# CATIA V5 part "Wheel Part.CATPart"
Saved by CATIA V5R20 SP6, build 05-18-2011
Part number: Wheel Part
Bounding box of the stored display mesh (mm): x -775 to 775, y -80 to 0, z 225 to 1775
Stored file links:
  E:\#01 CATIA Lecture Materials\#06 DMU\#01 DMU KIN Page01 EX01\#01 CATPart\Wheel Part.CATPart
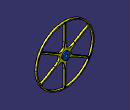
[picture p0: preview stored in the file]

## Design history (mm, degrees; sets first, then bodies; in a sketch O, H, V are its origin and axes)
Body1 (main body)
  Body2
    Sketch1 on zx-plane, origin (0, 0, 0), H (-1, 0, 0), V (0, 0, 1)
      circle A1 centre (0, 1000) radius 775
      arc A2 centre (0, 1000) radius 750 from (-35.959, 1749.1375) to (-630.7927, 1405.71) ccw
      point P1 (-35.959, 1749.1375)
      point P2 (-630.7927, 1405.71)
      line L1 (-15.0001, 1729.1605) -> (-15, 1307.7689)
      point P3 (-15.0001, 1729.1605)
      arc A3 centre (-515, 1307.8554) radius 500 from (-28.0077, 1194.5484) to (-15.0001, 1307.7689) ccw
      arc A4 centre (-9.1108, 1599.9308) radius 500 from (-259.1107, 1166.9181) to (-154.48, 1121.5296) ccw
      point P6 (-259.1107, 1166.9181)
      line L2 (-259.1107, 1166.9181) -> (-623.9715, 1377.5705)
      point P7 (-259.1107, 1166.9181)
      point P8 (-623.9715, 1377.5705)
      arc A5 centre (0, 1000) radius 750 from (-666.7516, 1343.4273) to (-666.7515, 656.5725) ccw
      point P9 (-666.7516, 1343.4273)
      point P10 (-666.7515, 656.5725)
      line L3 (-274.1107, 859.0626) -> (-638.9714, 648.4101)
      point P11 (-274.1107, 859.0626)
      point P12 (-638.9714, 648.4101)
      arc A6 centre (-524.1107, 1292.0753) radius 500 from (-274.1107, 859.0626) to (-182.4877, 926.9811) ccw
      point P13 (-274.1107, 859.0626)
      point P14 (-118.2881, 1000)
      arc A7 centre (-524.1106, 707.9246) radius 500 from (-182.4877, 1073.0188) to (-274.1622, 1140.9671) ccw
      point P15 (-118.2881, 1000)
      line L4 (-638.9715, 1351.5898) -> (-274.1622, 1140.9671)
      point P17 (-638.9715, 1351.5898)
      arc A8 centre (515, 1307.8556) radius 500 from (15, 1307.8555) to (28.0077, 1194.5484) ccw
      point P19 (15, 1307.8555)
      line L5 (15, 1307.8555) -> (14.9999, 1729.1605)
      point P20 (15, 1307.8555)
      point P21 (14.9999, 1729.1605)
      line L6 (623.9714, 1377.5707) -> (259.1106, 1166.9182)
      point P22 (623.9714, 1377.5707)
      point P23 (259.1106, 1166.9182)
      arc A9 centre (9.1106, 1599.9308) radius 500 from (154.48, 1121.5296) to (259.1106, 1166.9182) ccw
      point P24 (259.1106, 1166.9182)
      arc A10 centre (0, 1000) radius 750 from (630.7926, 1405.7102) to (35.9588, 1749.1375) ccw
      point P25 (630.7926, 1405.7102)
      point P26 (35.9588, 1749.1375)
      line L7 (274.1107, 1140.9374) -> (638.9714, 1351.5899)
      point P27 (274.1107, 1140.9374)
      point P28 (638.9714, 1351.5899)
      arc A11 centre (0, 1000) radius 750 from (666.7516, 656.5727) to (666.7515, 1343.4275) ccw
      point P29 (666.7516, 656.5727)
      point P30 (666.7515, 1343.4275)
      line L8 (638.9715, 648.4102) -> (274.1107, 859.0627)
      point P31 (638.9715, 648.4102)
      point P32 (274.1107, 859.0627)
      arc A12 centre (524.1106, 1292.0754) radius 500 from (182.4877, 926.9812) to (274.1107, 859.0627) ccw
      point P33 (274.1107, 859.0627)
      arc A13 centre (524.1107, 707.9247) radius 500 from (274.1107, 1140.9374) to (182.4877, 1073.0189) ccw
      point P34 (274.1107, 1140.9374)
      arc A14 centre (9.1108, 400.0692) radius 500 from (259.1715, 833.0468) to (154.48, 878.4704) ccw
      line L9 (259.1715, 833.0468) -> (623.9715, 622.4295)
      point P37 (623.9715, 622.4295)
      arc A15 centre (515, 692.1446) radius 500 from (28.0077, 805.4516) to (15, 692.1445) ccw
      point P38 (15, 692.1445)
      line L10 (15.0001, 270.8395) -> (15, 692.1445)
      point P39 (15.0001, 270.8395)
      point P40 (15, 692.1445)
      arc A16 centre (0, 1000) radius 750 from (35.959, 250.8625) to (630.7927, 594.29) ccw
      point P41 (35.959, 250.8625)
      point P42 (630.7927, 594.29)
      arc A17 centre (0, 1000) radius 750 from (-630.7926, 594.2898) to (-35.9588, 250.8625) ccw
      point P43 (-630.7926, 594.2898)
      point P44 (-35.9588, 250.8625)
      line L11 (-15, 692.0579) -> (-14.9999, 270.8395)
      point P46 (-14.9999, 270.8395)
      arc A18 centre (-515, 692.1444) radius 500 from (-15, 692.0579) to (-28.0077, 805.4516) ccw
      arc A19 centre (-9.1106, 400.0692) radius 500 from (-154.48, 878.4704) to (-259.1106, 833.0818) ccw
      point P48 (-259.1106, 833.0818)
      line L12 (-623.9714, 622.4293) -> (-259.1106, 833.0818)
      point P49 (-623.9714, 622.4293)
      point P50 (-259.1106, 833.0818)
      arc A20 centre (-35.0001, 1729.1605) radius 20 from (-15.0001, 1729.1605) to (-35.959, 1749.1375) ccw
      point P51 (-15.0001, 1729.1605)
      point P52 (-35.959, 1749.1375)
      circle A21 centre (-0.0001, 1750) radius 15
      arc A22 centre (34.9999, 1729.1605) radius 20 from (35.9588, 1749.1375) to (14.9999, 1729.1605) ccw
      point P53 (35.9588, 1749.1375)
      point P54 (14.9999, 1729.1605)
      circle A23 centre (-649.5191, 1374.9999) radius 15
      arc A24 centre (-613.9716, 1394.891) radius 20 from (-630.7927, 1405.71) to (-623.9715, 1377.5705) ccw
      point P55 (-630.7927, 1405.71)
      point P56 (-623.9715, 1377.5705)
      arc A25 centre (-648.9715, 1334.2693) radius 20 from (-638.9715, 1351.5898) to (-666.7516, 1343.4273) ccw
      point P57 (-638.9715, 1351.5898)
      point P58 (-666.7516, 1343.4273)
      circle A26 centre (-649.519, 624.9999) radius 15
      arc A27 centre (-613.9714, 605.1088) radius 20 from (-623.9714, 622.4293) to (-630.7926, 594.2898) ccw
      point P59 (-623.9714, 622.4293)
      point P60 (-630.7926, 594.2898)
      arc A28 centre (-648.9714, 665.7306) radius 20 from (-666.7515, 656.5725) to (-638.9714, 648.4101) ccw
      point P61 (-666.7515, 656.5725)
      point P62 (-638.9714, 648.4101)
      arc A29 centre (-34.9999, 270.8395) radius 20 from (-35.9588, 250.8625) to (-14.9999, 270.8395) ccw
      point P63 (-35.9588, 250.8625)
      point P64 (-14.9999, 270.8395)
      circle A30 centre (0.0001, 250) radius 15
      arc A31 centre (35.0001, 270.8395) radius 20 from (15.0001, 270.8395) to (35.959, 250.8625) ccw
      point P65 (15.0001, 270.8395)
      point P66 (35.959, 250.8625)
      arc A32 centre (648.9715, 665.7307) radius 20 from (638.9715, 648.4102) to (666.7516, 656.5727) ccw
      point P67 (638.9715, 648.4102)
      point P68 (666.7516, 656.5727)
      arc A33 centre (613.9716, 605.109) radius 20 from (630.7927, 594.29) to (623.9715, 622.4295) ccw
      point P69 (630.7927, 594.29)
      point P70 (623.9715, 622.4295)
      circle A34 centre (649.5191, 625.0001) radius 15
      circle A35 centre (649.519, 1375.0001) radius 15
      arc A36 centre (613.9714, 1394.8912) radius 20 from (623.9714, 1377.5707) to (630.7926, 1405.7102) ccw
      point P71 (623.9714, 1377.5707)
      point P72 (630.7926, 1405.7102)
      arc A37 centre (648.9714, 1334.2694) radius 20 from (666.7515, 1343.4275) to (638.9714, 1351.5899) ccw
      point P73 (666.7515, 1343.4275)
      point P74 (638.9714, 1351.5899)
      circle A38 centre (0, 1000) radius 100
      arc A39 centre (-125.4062, 1217.2098) radius 100 from (-28.0077, 1194.5484) to (-154.48, 1121.5296) cw
      arc A40 centre (125.4061, 1217.2098) radius 100 from (28.0077, 1194.5484) to (154.48, 1121.5296) ccw
      arc A41 centre (250.8123, 1000) radius 100 from (182.4877, 926.9812) to (182.4877, 1073.0189) cw
      arc A42 centre (125.4062, 782.7902) radius 100 from (154.48, 878.4704) to (28.0077, 805.4516) ccw
      arc A43 centre (-125.4061, 782.7902) radius 100 from (-28.0077, 805.4516) to (-154.48, 878.4704) ccw
      arc A44 centre (-250.8123, 1000) radius 100 from (-182.4877, 926.9811) to (-182.4877, 1073.0188) ccw
      radius A39 = 100
      radius A40 = 100 {= Sketch1.radius(A39)}
      radius A41 = 100 {= Sketch1.radius(A39)}
      radius A42 = 100 {= Sketch1.radius(A39)}
      radius A43 = 100 {= Sketch1.radius(A39)}
      radius A44 = 100
      tangency: A39 A3, A39 A4, A40 A8, A40 A9, A41 A12, A41 A13, A42 A14, A42 A15, A43 A18, A43 A19, A44 A6, A44 A7
      coincidence: P1 P52, P2 P55, P3 P51, P6 P7, P8 P56, P9 P58, P10 P61, P11 P13, P12 P62, P14 P15, P17 P57, P19 P20, P21 P54, P22 P71, P23 P24, P25 P72, P26 P53, P27 P34, P28 P74, P29 P68, P30 P73, P31 P67, P32 P33, P37 P70, P38 P40, P39 P65, P41 P66, P42 P69, P43 P60, P44 P63, P46 P64, P48 P50, P49 P59, A6 P14, A7 P15
    Pad1: profile Sketch1, direction (0, 1, 0), length 50
  Assemble1: tool Body2
  Body3
    Sketch2 on zx-plane, origin (0, 0, 0), H (-1, 0, 0), V (0, 0, 1)
      circle A1 centre (0, 1000) radius 100
      circle A2 centre (0, 1000) radius 40
    Pad2: profile Sketch2, direction (0, 1, 0), length 80
  Assemble2: tool Body3
  Translate1: ToTransfor Assemble2, Direction zx-plane, Length -80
